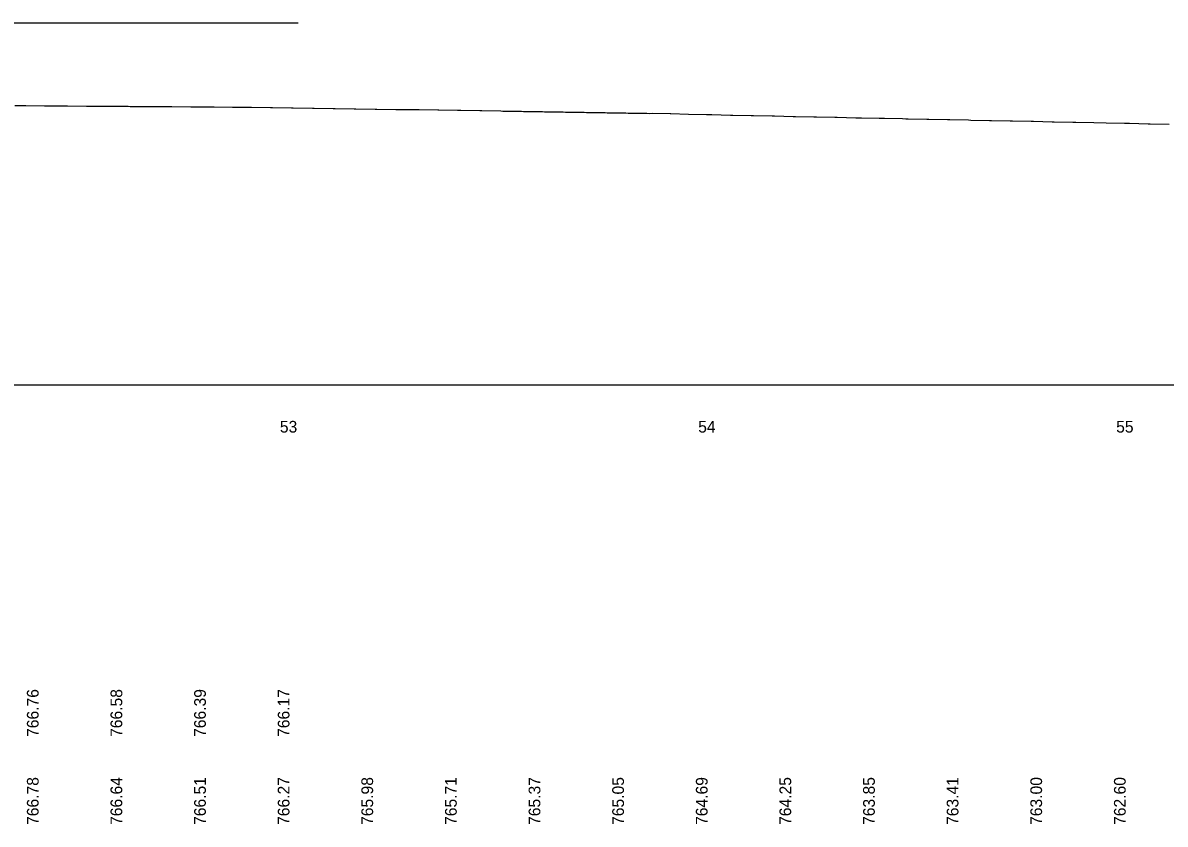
# Model space of a CAD drawing. Extents: x -209 to 3291, y 1080 to 3580.
# Drawn here: x 627.5 to 900.7, y 3225.1 to 3416.7 of the extents above; entities that cross this region are included whole.
import ezdxf

# ---------------------------------------------------------------- set-up
doc = ezdxf.new("R2010")
doc.units = 0
for name, color, linetype in [('GK_Cells', 7, 'Continuous'), ('PF_P_Sta_Elev_Text', 7, 'Continuous'), ('PF_P_Text', 7, 'Continuous'), ('PF_X_Ground_Line', 7, 'Continuous'), ('PF_X_Text', 7, 'Continuous')]:
    doc.layers.add(name, color=color, linetype=linetype)

msp = doc.modelspace()

# ---------------------------------------------------------------- linework, layer by layer
at = {"layer": 'GK_Cells'}
msp.add_line((-8.74, 3330.13), (3291.26, 3330.13), dxfattribs=at)
at = {"layer": 'PF_P_Text'}
msp.add_line((189.31, 3416.73), (693.33, 3416.73), dxfattribs=at)
at = {"layer": 'PF_X_Ground_Line'}
for points in [[(625.57, 3396.95), (627.69, 3396.94), (628.18, 3396.93), (632.69, 3396.9), (633.18, 3396.9), (637.69, 3396.87), (638.18, 3396.87), (642.69, 3396.84), (643.17, 3396.83), (647.69, 3396.8), (648.17, 3396.8), (652.69, 3396.77), (653.17, 3396.76), (657.69, 3396.73), (658.16, 3396.73), (662.69, 3396.7), (663.16, 3396.69), (667.69, 3396.66), (668.16, 3396.66), (672.69, 3396.63), (673.26, 3396.63), (677.67, 3396.6), (681.22, 3396.55), (681.73, 3396.54), (682.19, 3396.53), (686.73, 3396.47), (687.18, 3396.46), (691.73, 3396.39), (692.18, 3396.39), (696.73, 3396.32), (697.17, 3396.31), (701.73, 3396.25), (702.17, 3396.24), (706.73, 3396.18), (707.16, 3396.17), (711.73, 3396.11), (712.16, 3396.1), (716.73, 3396.04), (717.15, 3396.03), (721.73, 3395.97), (722.26, 3395.98), (726.72, 3395.91), (727.02, 3395.91), (731.46, 3395.84), (732.24, 3395.81), (736.8, 3395.73), (737.24, 3395.73), (741.79, 3395.65), (742.25, 3395.64), (746.77, 3395.57), (747.25, 3395.56), (751.76, 3395.49), (752.25, 3395.48), (756.75, 3395.41), (757.25, 3395.4), (761.74, 3395.33), (762.26, 3395.32), (766.73, 3395.25), (767.26, 3395.24), (771.72, 3395.17), (772.26, 3395.16), (776.71, 3395.09), (777.27, 3395.08), (778.02, 3395.09), (782.31, 3395.02), (782.44, 3395.01), (786.72, 3394.92), (790.99, 3394.83), (792.28, 3394.79), (796.71, 3394.69), (797.28, 3394.68), (801.71, 3394.59), (802.28, 3394.57), (806.71, 3394.48), (807.28, 3394.47), (811.71, 3394.37), (812.28, 3394.36), (816.71, 3394.27), (817.28, 3394.25), (821.7, 3394.16), (822.27, 3394.15), (826.7, 3394.05), (827.27, 3394.04), (828.04, 3394.05), (832.33, 3393.96), (833.59, 3393.93), (837.89, 3393.84), (838.66, 3393.8), (839.22, 3393.79)], [(839.22, 3393.79), (843.66, 3393.7), (844.21, 3393.69), (848.66, 3393.6), (849.21, 3393.59), (853.66, 3393.5), (854.2, 3393.49), (858.66, 3393.39), (859.2, 3393.38), (863.66, 3393.29), (864.19, 3393.28), (868.66, 3393.19), (869.18, 3393.18), (873.66, 3393.09), (874.18, 3393.08), (878.65, 3392.98), (879.31, 3392.99), (883.65, 3392.9), (886.61, 3392.83), (890.96, 3392.74), (891.62, 3392.71), (892.14, 3392.7), (896.62, 3392.6), (897.13, 3392.59), (901.62, 3392.5)]]:
    msp.add_lwpolyline(points, dxfattribs=at)

# ---------------------------------------------------------------- texts
at = {"layer": 'PF_P_Sta_Elev_Text'}
for s, p in [('53', (688.96, 3318.73)), ('53', (688.96, 3318.73)), ('54', (789.01, 3318.73)), ('55', (888.98, 3318.73))]:
    msp.add_text(s, height=2.8, dxfattribs=at).set_placement(p)
at = {"layer": 'PF_P_Text'}
for s, p in [('766.76', (631.26, 3245.93)), ('766.58', (651.26, 3245.93)), ('766.39', (671.26, 3245.93)), ('766.17', (691.26, 3245.93))]:
    msp.add_text(s, height=2.8, rotation=90, dxfattribs=at).set_placement(p)
at = {"layer": 'PF_X_Text'}
for s, p in [('766.78', (631.26, 3224.88)), ('766.64', (651.26, 3224.88)), ('766.51', (671.26, 3224.88)), ('766.27', (691.26, 3224.88)), ('765.98', (711.26, 3224.88)), ('765.71', (731.26, 3224.88)), ('765.37', (751.26, 3224.88)), ('765.05', (771.26, 3224.88)), ('764.69', (791.26, 3224.88)), ('764.25', (811.26, 3224.88)), ('763.85', (831.26, 3224.88)), ('763.41', (851.26, 3224.88)), ('763.00', (871.26, 3224.88)), ('762.60', (891.26, 3224.88))]:
    msp.add_text(s, height=2.8, rotation=90, dxfattribs=at).set_placement(p)

doc.saveas('drawing.dxf')
